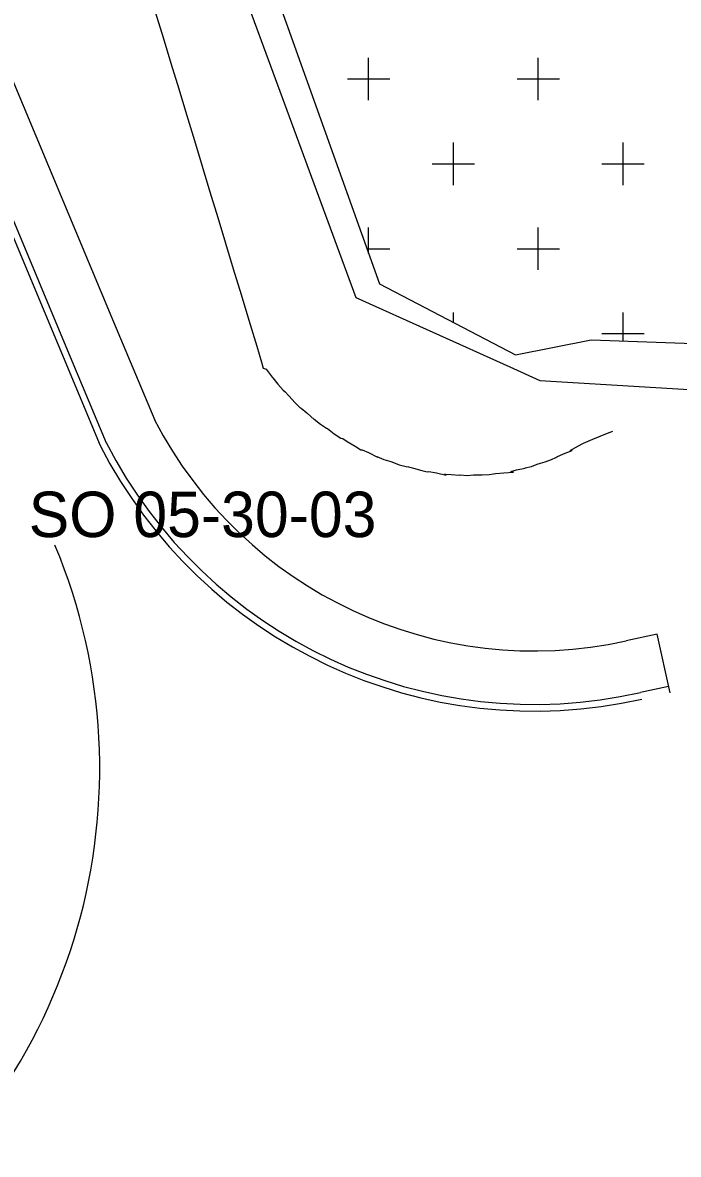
# Model space of a CAD drawing. Extents: x -723225 to -722352, y -1040354 to -1039760.
# Drawn here: x -722642.16 to -722617.61, y -1040011.49 to -1039969.14 of the extents above; entities that cross this region are included whole.
import ezdxf

# ---------------------------------------------------------------- set-up
doc = ezdxf.new("R2010")
doc.units = 0
for name, color, linetype in [('_PS_SO_číslo', 7, 'Continuous'), ('SO 00_82_01', 7, 'Continuous'), ('SO 05_30_03', 7, 'Continuous'), ('SO 05_73_06', 7, 'Continuous')]:
    doc.layers.add(name, color=color, linetype=linetype)

msp = doc.modelspace()

# ---------------------------------------------------------------- linework, layer by layer
at = {"layer": 'SO 00_82_01'}
for p, q in [((-722629.206, -1039972.044), (-722629.206, -1039970.456)), ((-722622.856, -1039972.044), (-722622.856, -1039970.456)), ((-722630, -1039971.25), (-722628.413, -1039971.25)), ((-722623.65, -1039971.25), (-722622.063, -1039971.25)), ((-722626.031, -1039975.219), (-722626.031, -1039973.631)), ((-722619.681, -1039975.219), (-722619.681, -1039973.631)), ((-722626.825, -1039974.425), (-722625.238, -1039974.425)), ((-722620.475, -1039974.425), (-722618.888, -1039974.425)), ((-722629.206, -1039977.782), (-722629.206, -1039976.806)), ((-722622.856, -1039978.394), (-722622.856, -1039976.806)), ((-722629.271, -1039977.6), (-722628.413, -1039977.6)), ((-722623.65, -1039977.6), (-722622.063, -1039977.6)), ((-722626.031, -1039980.358), (-722626.031, -1039979.981)), ((-722619.681, -1039981.058), (-722619.681, -1039979.981)), ((-722620.475, -1039980.775), (-722618.888, -1039980.775))]:
    msp.add_line(p, q, dxfattribs=at)
msp.add_lwpolyline([(-722622.138, -1039926.562), (-722638.89, -1039939.47), (-722642.043, -1039941.899), (-722628.802, -1039978.912), (-722623.71, -1039981.569), (-722620.88, -1039981.015), (-722605.934, -1039981.545), (-722600.545, -1039982.372), (-722622.138, -1039926.562)], dxfattribs=at)
at = {"layer": 'SO 05_30_03'}
for p, q in [((-722618.406, -1039992.022), (-722619.57, -1039992.278)), ((-722617.924, -1039994.22), (-722618.406, -1039992.022)), ((-722617.978, -1039993.976), (-722619.035, -1039994.208))]:
    msp.add_line(p, q, dxfattribs=at)
for points in [[(-722645.991, -1039963.013), (-722642.609, -1039971.105), (-722638.752, -1039980.332), (-722637.214, -1039984.01)], [(-722648.068, -1039963.882), (-722644.685, -1039971.974), (-722640.829, -1039981.2), (-722639.258, -1039984.958)], [(-722647.837, -1039963.785), (-722644.455, -1039971.877), (-722640.598, -1039981.104), (-722639.027, -1039984.862)], [(-722637.201, -1039968.742), (-722636.895, -1039969.698), (-722636.604, -1039970.66), (-722636.312, -1039971.622), (-722636.02, -1039972.584), (-722635.729, -1039973.546), (-722635.437, -1039974.508), (-722635.146, -1039975.469), (-722634.854, -1039976.431), (-722634.562, -1039977.393), (-722634.271, -1039978.355), (-722633.979, -1039979.317), (-722633.687, -1039980.279), (-722633.396, -1039981.241), (-722633.219, -1039981.851), (-722633.148, -1039982.069), (-722633.043, -1039982.106), (-722632.823, -1039982.405), (-722632.795, -1039982.427), (-722632.609, -1039982.67), (-722632.407, -1039982.892), (-722632.329, -1039982.958), (-722632.196, -1039983.103), (-722631.952, -1039983.362), (-722631.779, -1039983.541), (-722631.731, -1039983.567), (-722631.516, -1039983.738), (-722631.238, -1039984), (-722631.247, -1039983.978), (-722631.01, -1039984.165), (-722630.784, -1039984.312), (-722630.745, -1039984.332), (-722630.498, -1039984.524), (-722630.248, -1039984.685), (-722630.177, -1039984.706), (-722630.013, -1039984.808), (-722629.71, -1039984.994), (-722629.495, -1039985.123), (-722629.453, -1039985.126), (-722629.213, -1039985.222), (-722628.873, -1039985.405), (-722628.895, -1039985.379), (-722628.634, -1039985.482), (-722628.379, -1039985.562), (-722628.332, -1039985.573), (-722628.061, -1039985.682), (-722627.799, -1039985.753), (-722627.713, -1039985.761), (-722627.527, -1039985.817), (-722627.215, -1039985.9), (-722627.01, -1039985.943), (-722626.957, -1039985.94), (-722626.666, -1039985.987), (-722626.304, -1039986.068), (-722626.366, -1039986.033), (-722626.115, -1039986.044), (-722625.807, -1039986.07), (-722625.778, -1039986.063), (-722625.523, -1039986.082), (-722625.282, -1039986.066), (-722625.15, -1039986.063), (-722624.962, -1039986.067), (-722624.693, -1039986.049), (-722624.529, -1039986.021), (-722624.463, -1039986.008), (-722624.14, -1039985.981), (-722623.788, -1039985.958), (-722623.885, -1039985.936), (-722623.667, -1039985.873), (-722623.351, -1039985.816), (-722623.341, -1039985.8), (-722623.106, -1039985.747), (-722622.898, -1039985.664), (-722622.773, -1039985.625), (-722622.604, -1039985.577), (-722622.361, -1039985.485), (-722622.201, -1039985.413), (-722622.163, -1039985.384), (-722621.907, -1039985.273), (-722621.582, -1039985.152), (-722621.658, -1039985.156), (-722621.467, -1039985.038), (-722621.212, -1039984.9), (-722621.16, -1039984.873), (-722620.817, -1039984.731), (-722620.264, -1039984.505), (-722620.071, -1039984.428)]]:
    msp.add_lwpolyline(points, dxfattribs=at)
for centre, radius, start, end in [((-722623.008, -1039976.654), 15.997, 207.3589, 282.4093), ((-722623.008, -1039976.651), 18.25, 207.0756, 282.7514), ((-722623.008, -1039976.651), 18, 207.106, 282.7514), ((-722660.941, -1039997.051), 21.669, 305.236, 22.6857)]:
    msp.add_arc(centre, radius, start, end, dxfattribs=at)
at = {"layer": 'SO 05_73_06'}
msp.add_lwpolyline([(-722640.666, -1039949.617), (-722629.68, -1039979.429), (-722623.915, -1039982.026), (-722622.793, -1039982.53), (-722605.848, -1039983.549), (-722601.728, -1039984.186), (-722581.726, -1039987.283), (-722548.111, -1040039.79)], dxfattribs=at)

# ---------------------------------------------------------------- texts
at = {"layer": '_PS_SO_číslo'}
msp.add_text('SO 05-30-03', height=1.7, dxfattribs=at).set_placement((-722641.93, -1039988.39))

doc.saveas('drawing.dxf')
